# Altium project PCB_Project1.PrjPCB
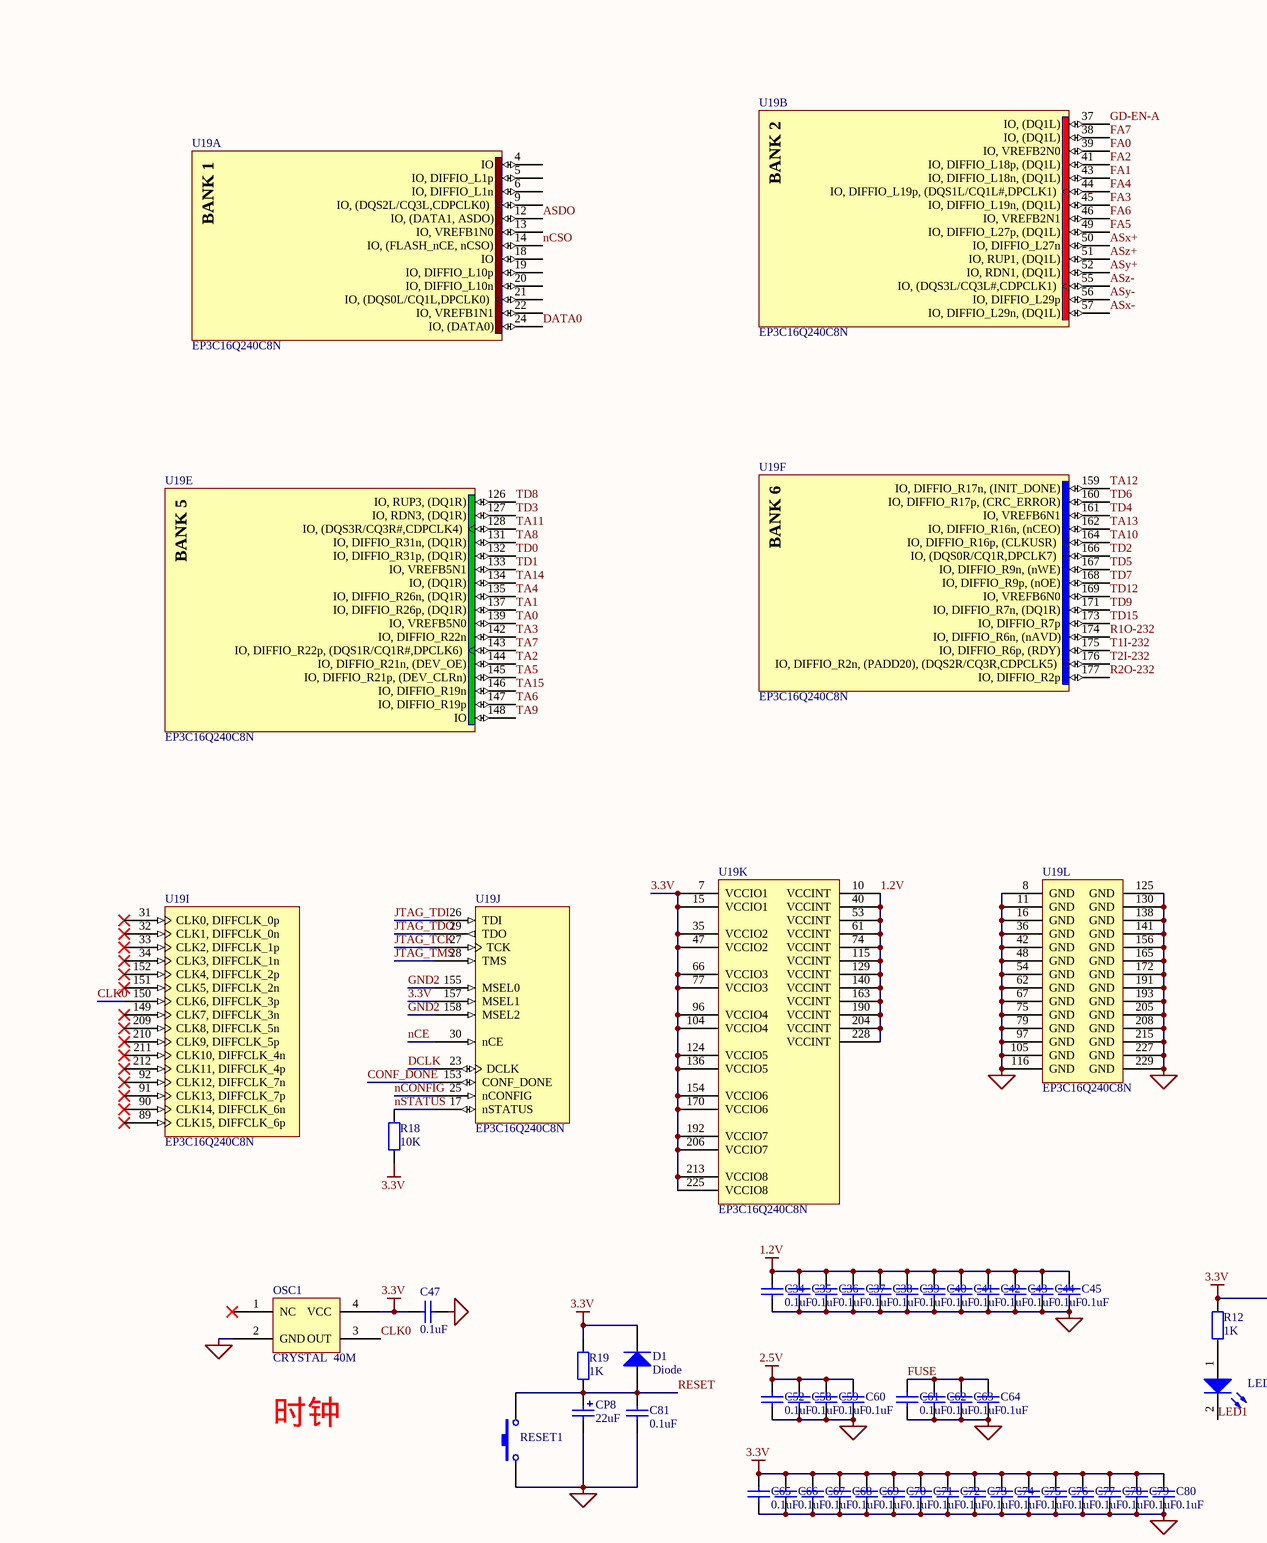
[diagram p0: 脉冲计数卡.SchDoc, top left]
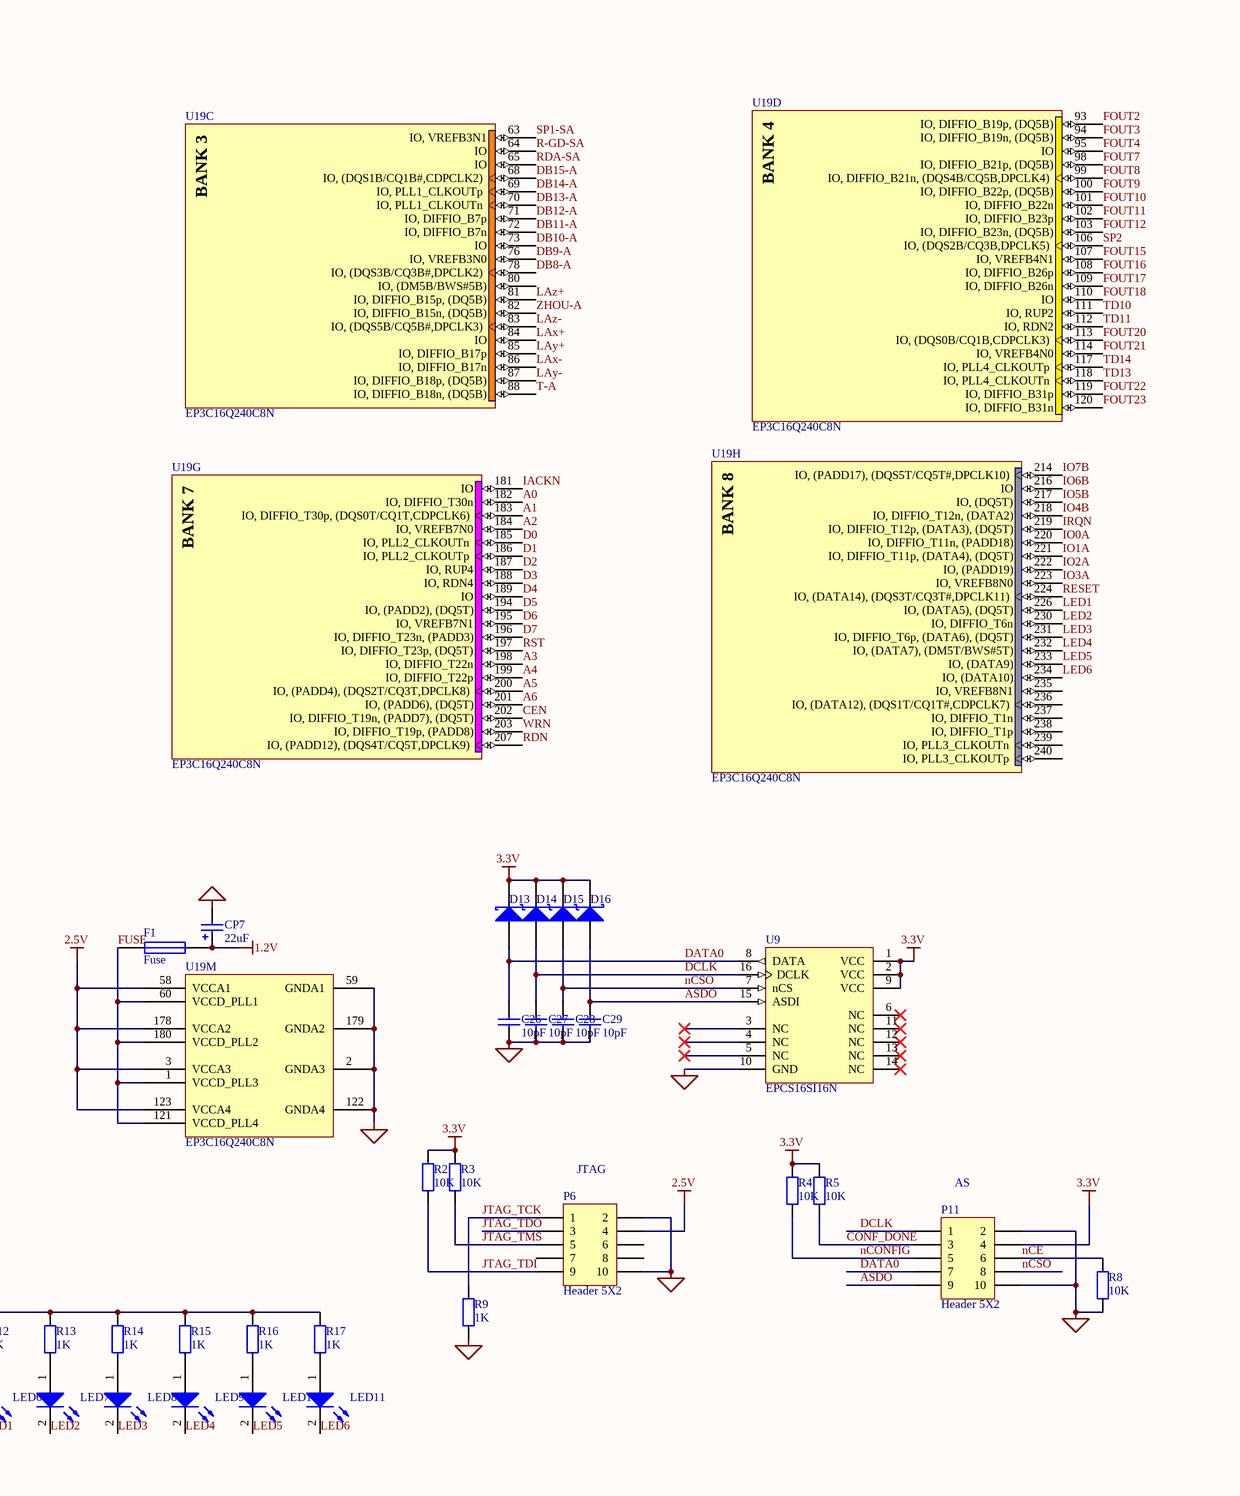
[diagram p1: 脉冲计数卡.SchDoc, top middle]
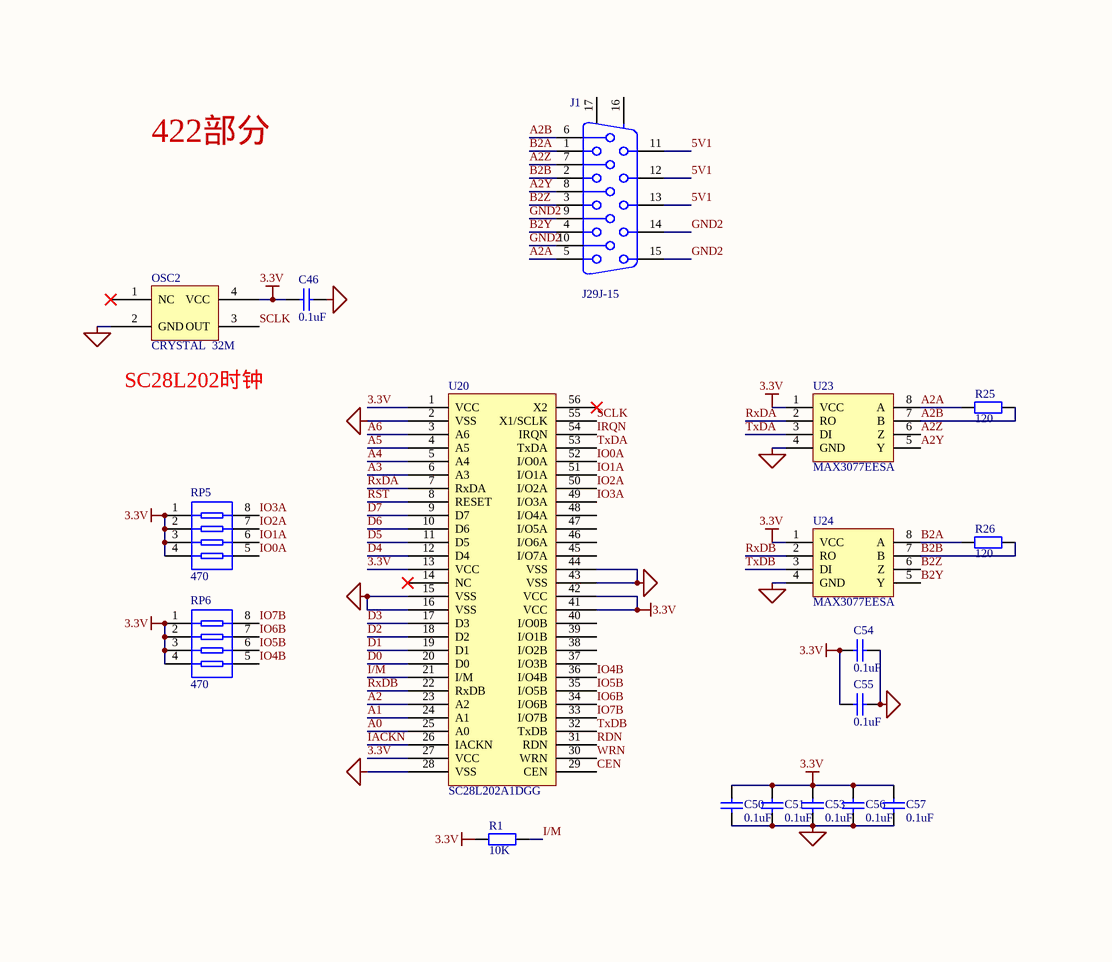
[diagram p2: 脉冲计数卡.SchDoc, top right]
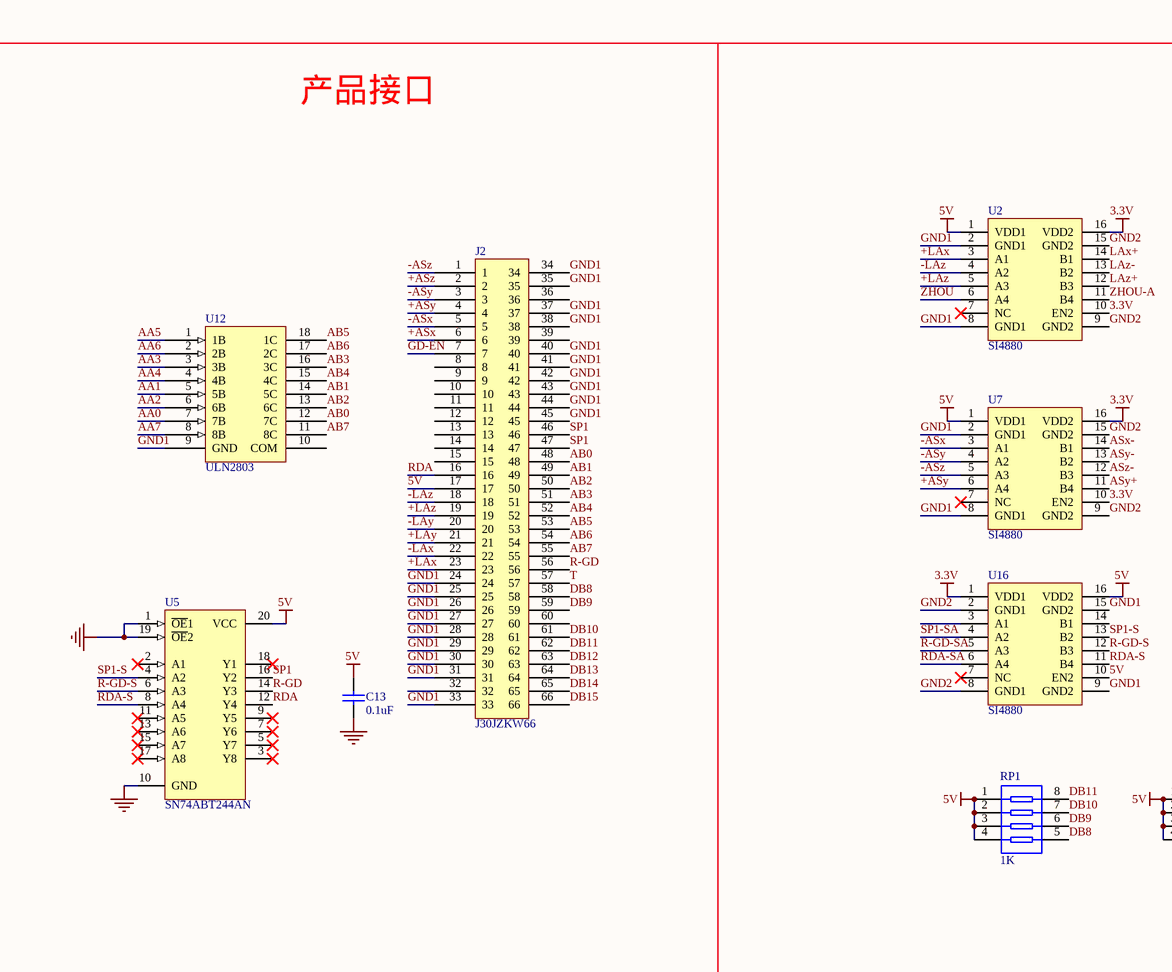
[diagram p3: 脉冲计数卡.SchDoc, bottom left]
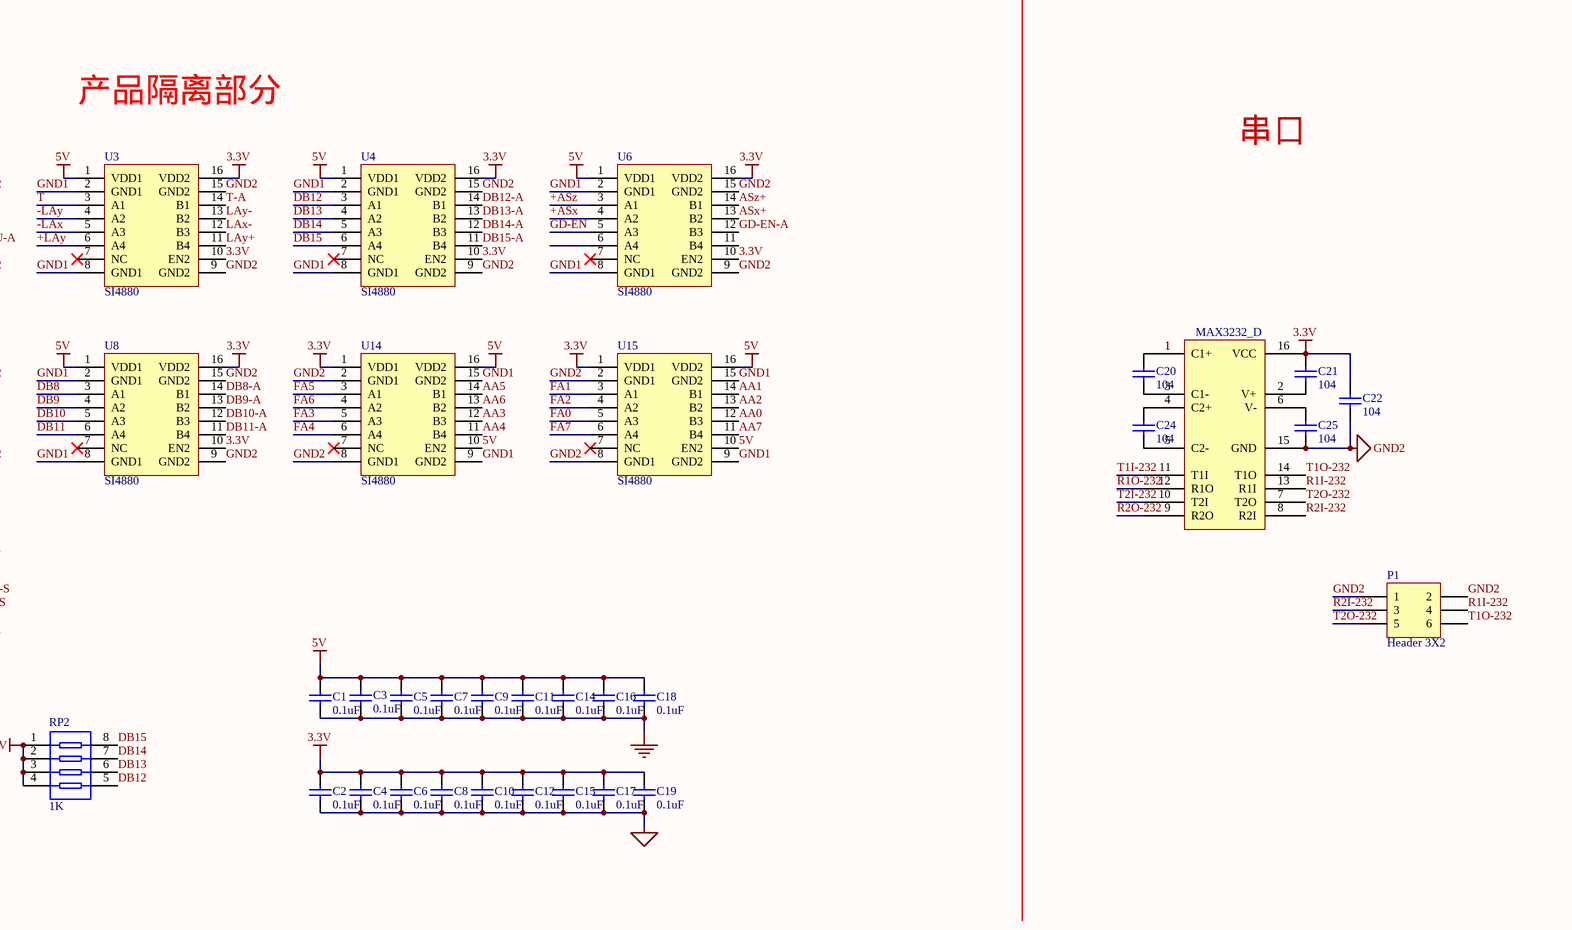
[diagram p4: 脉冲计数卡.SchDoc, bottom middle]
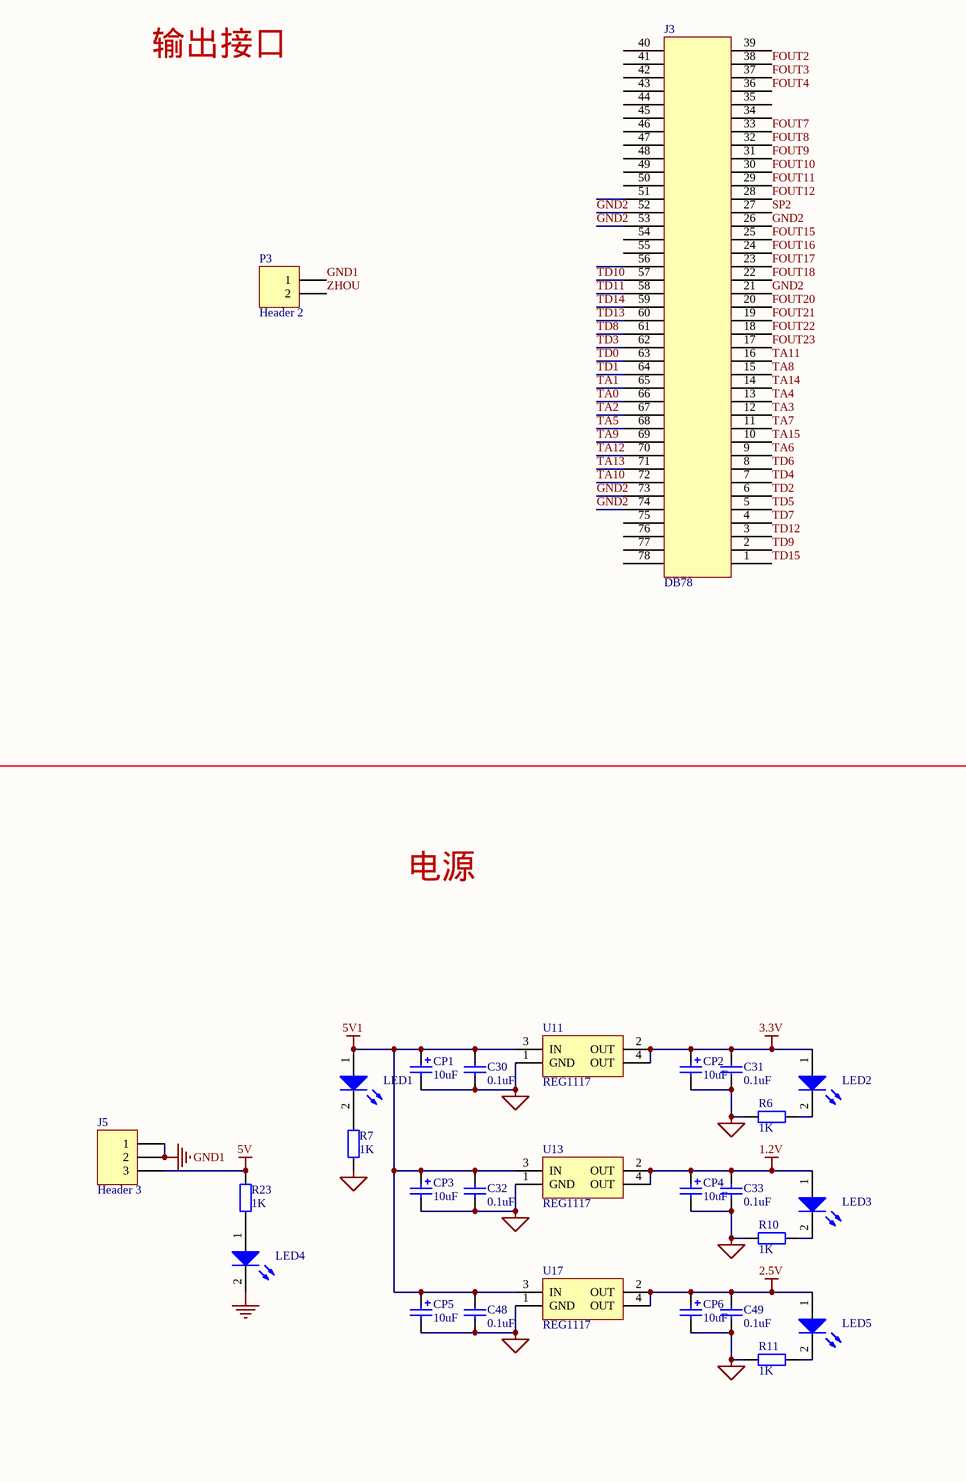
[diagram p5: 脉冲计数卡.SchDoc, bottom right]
1 sheet, 162 parts. Net scope: global (net labels, ports and power ports of the same name join across sheets).
Board file: 脉冲计数卡.PcbDoc

## Sheet 脉冲计数卡.SchDoc
size A1

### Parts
C1  0.1uF  [1608[0603]]
C2  0.1uF  [1608[0603]]
C3  0.1uF  [1608[0603]]
C4  0.1uF  [1608[0603]]
C5  0.1uF  [1608[0603]]
C6  0.1uF  [1608[0603]]
C7  0.1uF  [1608[0603]]
C8  0.1uF  [1608[0603]]
C9  0.1uF  [1608[0603]]
C10  0.1uF  [1608[0603]]
C11  0.1uF  [1608[0603]]
C12  0.1uF  [1608[0603]]
C13  0.1uF  [1608[0603]]
C14  0.1uF  [1608[0603]]
C15  0.1uF  [1608[0603]]
C16  0.1uF  [1608[0603]]
C17  0.1uF  [1608[0603]]
C18  0.1uF  [1608[0603]]
C19  0.1uF  [1608[0603]]
C20  104  [1608[0603]]
C21  104  [1608[0603]]
C22  104  [1608[0603]]
C24  104  [1608[0603]]
C25  104  [1608[0603]]
C26  10pF  [1608[0603]]
C27  10pF  [1608[0603]]
C28  10pF  [1608[0603]]
C29  10pF  [1608[0603]]
C30  0.1uF  [1608[0603]]
C31  0.1uF  [1608[0603]]
C32  0.1uF  [1608[0603]]
C33  0.1uF  [1608[0603]]
C34  0.1uF  [1608[0603]]
C35  0.1uF  [1608[0603]]
C36  0.1uF  [1608[0603]]
C37  0.1uF  [1608[0603]]
C38  0.1uF  [1608[0603]]
C39  0.1uF  [1608[0603]]
C40  0.1uF  [1608[0603]]
C41  0.1uF  [1608[0603]]
C42  0.1uF  [1608[0603]]
C43  0.1uF  [1608[0603]]
C44  0.1uF  [1608[0603]]
C45  0.1uF  [1608[0603]]
C46  0.1uF  [1608[0603]]
C47  0.1uF  [1608[0603]]
C48  0.1uF  [1608[0603]]
C49  0.1uF  [1608[0603]]
C50  0.1uF  [1608[0603]]
C51  0.1uF  [1608[0603]]
C52  0.1uF  [1608[0603]]
C53  0.1uF  [1608[0603]]
C54  0.1uF  [1608[0603]]
C55  0.1uF  [1608[0603]]
C56  0.1uF  [1608[0603]]
C57  0.1uF  [1608[0603]]
C58  0.1uF  [1608[0603]]
C59  0.1uF  [1608[0603]]
C60  0.1uF  [1608[0603]]
C61  0.1uF  [1608[0603]]
C62  0.1uF  [1608[0603]]
C63  0.1uF  [1608[0603]]
C64  0.1uF  [1608[0603]]
C65  0.1uF  [1608[0603]]
C66  0.1uF  [1608[0603]]
C67  0.1uF  [1608[0603]]
C68  0.1uF  [1608[0603]]
C69  0.1uF  [1608[0603]]
C70  0.1uF  [1608[0603]]
C71  0.1uF  [1608[0603]]
C72  0.1uF  [1608[0603]]
C73  0.1uF  [1608[0603]]
C74  0.1uF  [1608[0603]]
C75  0.1uF  [1608[0603]]
C76  0.1uF  [1608[0603]]
C77  0.1uF  [1608[0603]]
C78  0.1uF  [1608[0603]]
C79  0.1uF  [1608[0603]]
C80  0.1uF  [1608[0603]]
C81  0.1uF  [1608[0603]]
CP1  10uF  [C1210]
CP2  10uF  [C1210]
CP3  10uF  [C1210]
CP4  10uF  [C1210]
CP5  10uF  [C1210]
CP6  10uF  [C1210]
CP7  22uF  [C1210]
CP8  22uF  [C1210]
D1  Diode  [DSO-C2/X3.3]
D13  D Schottky  [SMB]  (value not drawn)
D14  D Schottky  [SMB]  (value not drawn)
D15  D Schottky  [SMB]  (value not drawn)
D16  D Schottky  [SMB]  (value not drawn)
F1  Fuse  [R2012-0805]
J1  J29J-15  [J29J-15]
J2  J30JZKW66  [J30J-66ZKW2]
J3  DB78  [DB78]
J5  Header 3  [POWER_CON]
LED1  LED12V  [R2012-0805]  (value not drawn)
LED2  LED12V  [R2012-0805]  (value not drawn)
LED3  LED12V  [R2012-0805]  (value not drawn)
LED4  LED12V  [R2012-0805]  (value not drawn)
LED5  LED12V  [R2012-0805]  (value not drawn)
LED6  LED12V  [R2012-0805]  (value not drawn)
LED7  LED12V  [R2012-0805]  (value not drawn)
LED8  LED12V  [R2012-0805]  (value not drawn)
LED9  LED12V  [R2012-0805]  (value not drawn)
LED10  LED12V  [R2012-0805]  (value not drawn)
LED11  LED12V  [R2012-0805]  (value not drawn)
MAX3232_D  SP3232E  [SOJ-16_2]  (value not drawn)
OSC1  CRYSTAL  40M  [OSC]
OSC2  CRYSTAL  32M  [OSC]
P1  Header 3X2  [HDR2X3]
P3  Header 2  [HDR1X2]
P6  Header 5X2  [FPGA_LOAD]
P11  Header 5X2  [FPGA_LOAD]
R1  10K  [1608[0603]]
R2  10K  [1608[0603]]
R3  10K  [1608[0603]]
R4  10K  [1608[0603]]
R5  10K  [1608[0603]]
R6  1K  [1608[0603]]
R7  1K  [1608[0603]]
R8  10K  [1608[0603]]
R9  1K  [1608[0603]]
R10  1K  [1608[0603]]
R11  1K  [1608[0603]]
R12  1K  [R2012-0805]
R13  1K  [R2012-0805]
R14  1K  [R2012-0805]
R15  1K  [R2012-0805]
R16  1K  [R2012-0805]
R17  1K  [R2012-0805]
R18  10K  [1608[0603]]
R19  1K  [1608[0603]]
R23  1K  [1608[0603]]
R25  120  [1608[0603]]
R26  120  [1608[0603]]
RESET1  SW  [SW4]  (value not drawn)
RP1  1K  [RP8]
RP2  1K  [RP8]
RP5  470  [RP8]
RP6  470  [RP8]
U2  SI4880  [RW-16]
U3  SI4880  [RW-16]
U4  SI4880  [RW-16]
U5  SN74ABT244AN  [SN74ABT244ADW--SOIC20]
U6  SI4880  [RW-16]
U7  SI4880  [RW-16]
U8  SI4880  [RW-16]
U9  EPCS16SI16N  [SOIC16_L]
U11  REG1117  [ZZ311]
U12  ULN2803  [ULN2803AFWG--SOIC18]
U13  REG1117  [ZZ311]
U14  SI4880  [RW-16]
U15  SI4880  [RW-16]
U16  SI4880  [RW-16]
U17  REG1117  [ZZ311]
U19  EP3C16Q240C8N  [PQFP240_N]  (parts A,B,C,D,E,F,G,H,I,J,K,L,M of 13)
U20  SC28L202A1DGG  [TSSOP56]
U23  MAX3077EESA  [DIP8]
U24  MAX3077EESA  [DIP8]

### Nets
1.2V: C33.2 C34.2 C35.2 C36.2 C37.2 C38.2 C39.2 C40.2 C41.2 C42.2 C43.2 C44.2 C45.2 CP4.1 CP7.1 F1.2 LED3.1(A) U13.2(OUT) U13.4(OUT) U19.10(VCCINT) U19.40(VCCINT) U19.53(VCCINT) U19.61(VCCINT) U19.74(VCCINT) U19.115(VCCINT) U19.129(VCCINT) U19.140(VCCINT) U19.163(VCCINT) U19.190(VCCINT) U19.204(VCCINT) U19.228(VCCINT)
2.5V: C49.2 C52.2 C58.2 C59.2 C60.2 CP6.1 LED5.1(A) P6.4 U17.2(OUT) U17.4(OUT) U19.3(VCCA3) U19.58(VCCA1) U19.123(VCCA4) U19.178(VCCA2)
3.3V: C2.2 C4.2 C6.2 C8.2 C10.2 C12.2 C15.2 C17.2 C19.2 C21.2 C22.2 C31.2 C46.1 C47.1 C50.2 C51.2 C53.2 C54.1 C55.1 C56.2 C57.1 C65.2 C66.2 C67.2 C68.2 C69.2 C70.2 C71.2 C72.2 C73.2 C74.2 C75.2 C76.2 C77.2 C78.2 C79.2 C80.2 CP2.1 D1.2(K) D13.2(K) D14.2(K) D15.2(K) D16.2(K) LED2.1(A) MAX3232_D.16(VCC) OSC1.4(VCC) OSC2.4(VCC) P11.4 R1.1 R2.2 R3.2 R4.2 R5.2 R12.2 R13.2 R14.2 R15.2 R16.2 R17.2 R18.1 R19.2 RP5.1 RP5.2 RP5.3 RP5.4 RP6.1 RP6.2 RP6.3 RP6.4 U2.10(EN2) U2.16(VDD2) U3.10(EN2) U3.16(VDD2) U4.10(EN2) U4.16(VDD2) U6.10(EN2) U6.16(VDD2) U7.10(EN2) U7.16(VDD2) U8.10(EN2) U8.16(VDD2) U9.1(VCC) U9.2(VCC) U9.9(VCC) U11.2(OUT) U11.4(OUT) U14.1(VDD1) U15.1(VDD1) U16.1(VDD1) U19.7(VCCIO1) U19.15(VCCIO1) U19.35(VCCIO2) U19.47(VCCIO2) U19.66(VCCIO3) U19.77(VCCIO3) U19.96(VCCIO4) U19.104(VCCIO4) U19.124(VCCIO5) U19.136(VCCIO5) U19.154(VCCIO6) U19.157(MSEL1) U19.170(VCCIO6) U19.192(VCCIO7) U19.206(VCCIO7) U19.213(VCCIO8) U19.225(VCCIO8) U20.1(VCC) U20.13(VCC) U20.27(VCC) U20.41(VCC) U20.42(VCC) U23.1(VCC) U24.1(VCC)
5V: C1.2 C3.2 C5.2 C7.2 C9.2 C11.2 C13.2 C14.2 C16.2 C18.2 J2.17 J5.3 R23.2 RP1.1 RP1.2 RP1.3 RP1.4 RP2.1 RP2.2 RP2.3 RP2.4 U2.1(VDD1) U3.1(VDD1) U4.1(VDD1) U5.20(VCC) U6.1(VDD1) U7.1(VDD1) U8.1(VDD1) U14.10(EN2) U14.16(VDD2) U15.10(EN2) U15.16(VDD2) U16.10(EN2) U16.16(VDD2)
5V1: C30.2 C32.2 C48.2 CP1.1 CP3.1 CP5.1 J1.11 J1.12 J1.13 LED1.1(A) U11.3(IN) U13.3(IN) U17.3(IN)
GND1: C1.1 C3.1 C5.1 C7.1 C9.1 C11.1 C13.1 C14.1 C16.1 C18.1 J2.24 J2.25 J2.26 J2.27 J2.28 J2.29 J2.30 J2.31 J2.33 J2.34 J2.35 J2.37 J2.38 J2.40 J2.41 J2.42 J2.43 J2.44 J2.45 J5.1 J5.2 LED4.2(K) P3.1 U2.2(GND1) U2.8(GND1) U3.2(GND1) U3.8(GND1) U4.2(GND1) U4.8(GND1) U5.1(~{OE}1) U5.10(GND) U5.19(~{OE}2) U6.2(GND1) U6.8(GND1) U7.2(GND1) U7.8(GND1) U8.2(GND1) U8.8(GND1) U12.9(GND) U14.9(GND2) U14.15(GND2) U15.9(GND2) U15.15(GND2) U16.9(GND2) U16.15(GND2)
GND2: C2.1 C4.1 C6.1 C8.1 C10.1 C12.1 C15.1 C17.1 C19.1 C22.1 C25.1 C26.1 C27.1 C28.1 C29.1 C30.1 C31.1 C32.1 C33.1 C34.1 C35.1 C36.1 C37.1 C38.1 C39.1 C40.1 C41.1 C42.1 C43.1 C44.1 C45.1 C46.2 C47.2 C48.1 C49.1 C50.1 C51.1 C52.1 C53.1 C54.2 C55.2 C56.1 C57.2 C58.1 C59.1 C60.1 C61.1 C62.1 C63.1 C64.1 C65.1 C66.1 C67.1 C68.1 C69.1 C70.1 C71.1 C72.1 C73.1 C74.1 C75.1 C76.1 C77.1 C78.1 C79.1 C80.1 C81.1 CP1.2 CP2.2 CP3.2 CP4.2 CP5.2 CP6.2 CP7.2 CP8.2 J1.9 J1.10 J1.14 J1.15 J3.21 J3.26 J3.52 J3.53 J3.73 J3.74 MAX3232_D.15(GND) OSC1.2(GND) OSC2.2(GND) P1.1 P1.2 P6.2 P6.10 P11.2 P11.10 R6.2 R7.2 R8.1 R9.1 R10.2 R11.2 RESET1.1 U2.9(GND2) U2.15(GND2) U3.9(GND2) U3.15(GND2) U4.9(GND2) U4.15(GND2) U6.9(GND2) U6.15(GND2) U7.9(GND2) U7.15(GND2) U8.9(GND2) U8.15(GND2) U9.10(GND) U11.1(GND) U13.1(GND) U14.2(GND1) U14.8(GND1) U15.2(GND1) U15.8(GND1) U16.2(GND1) U16.8(GND1) U17.1(GND) U19.2(GNDA3) U19.8(GND) U19.11(GND) U19.16(GND) U19.36(GND) U19.42(GND) U19.48(GND) U19.54(GND) U19.59(GNDA1) U19.62(GND) U19.67(GND) U19.75(GND) U19.79(GND) U19.97(GND) U19.105(GND) U19.116(GND) U19.122(GNDA4) U19.125(GND) U19.130(GND) U19.138(GND) U19.141(GND) U19.155(MSEL0) U19.156(GND) U19.158(MSEL2) U19.165(GND) U19.172(GND) U19.179(GNDA2) U19.191(GND) U19.193(GND) U19.205(GND) U19.208(GND) U19.215(GND) U19.227(GND) U19.229(GND) U20.2(VSS) U20.15(VSS) U20.16(VSS) U20.28(VSS) U20.43(VSS) U20.44(VSS) U23.4(GND) U24.4(GND)
+ASx: J2.6 U6.4(A2)
+ASy: J2.4 U7.6(A4)
+ASz: J2.2 U6.3(A1)
+LAx: J2.23 U2.3(A1)
+LAy: J2.21 U3.6(A4)
+LAz: J2.19 U2.5(A3)
-ASx: J2.5 U7.3(A1)
-ASy: J2.3 U7.4(A2)
-ASz: J2.1 U7.5(A3)
-LAx: J2.22 U3.5(A3)
-LAy: J2.20 U3.4(A2)
-LAz: J2.18 U2.4(A2)
A0: U19.182(IO,_DIFFIO_T30n) U20.25(A0)
A1: U19.183(IO,_DIFFIO_T30p,_(DQS0T/CQ1T,CDPCLK6)) U20.24(A1)
A2: U19.184(IO,_VREFB7N0) U20.23(A2)
A2A: J1.5 R25.1 U23.8(A)
A2B: J1.6 R25.2 U23.7(B)
A2Y: J1.8 U23.5(Y)
A2Z: J1.7 U23.6(Z)
A3: U19.198(IO,_DIFFIO_T22n) U20.6(A3)
A4: U19.199(IO,_DIFFIO_T22p) U20.5(A4)
A5: U19.200(IO,_(PADD4),_(DQS2T/CQ3T,DPCLK8)) U20.4(A5)
A6: U19.201(IO,_(PADD6),_(DQ5T)) U20.3(A6)
AA0: U12.7(7B) U15.12(B3)
AA1: U12.5(5B) U15.14(B1)
AA2: U12.6(6B) U15.13(B2)
AA3: U12.3(3B) U14.12(B3)
AA4: U12.4(4B) U14.11(B4)
AA5: U12.1(1B) U14.14(B1)
AA6: U12.2(2B) U14.13(B2)
AA7: U12.8(8B) U15.11(B4)
AB0: J2.48 U12.12(7C)
AB1: J2.49 U12.14(5C)
AB2: J2.50 U12.13(6C)
AB3: J2.51 U12.16(3C)
AB4: J2.52 U12.15(4C)
AB5: J2.53 U12.18(1C)
AB6: J2.54 U12.17(2C)
AB7: J2.55 U12.11(8C)
ASDO: C29.2 D16.1(A) P11.9 U9.15(ASDI) U19.12(IO,_(DATA1,_ASDO))
ASx+: U6.13(B2) U19.50(IO,_DIFFIO_L27n)
ASx-: U7.14(B1) U19.57(IO,_DIFFIO_L29n,_(DQ1L))
ASy+: U7.11(B4) U19.52(IO,_RDN1,_(DQ1L))
ASy-: U7.13(B2) U19.56(IO,_DIFFIO_L29p)
ASz+: U6.14(B1) U19.51(IO,_RUP1,_(DQ1L))
ASz-: U7.12(B3) U19.55(IO,_(DQS3L/CQ3L#,CDPCLK1))
B2A: J1.1 R26.1 U24.8(A)
B2B: J1.2 R26.2 U24.7(B)
B2Y: J1.4 U24.5(Y)
B2Z: J1.3 U24.6(Z)
CEN: U19.202(IO,_DIFFIO_T19n,_(PADD7),_(DQ5T)) U20.29(CEN)
CLK0: OSC1.3(OUT) U19.150(CLK6,_DIFFCLK_3p)
CONF_DONE: P11.3 R5.1 U19.153(CONF_DONE)
D0: U19.185(IO,_PLL2_CLKOUTn) U20.20(D0)
D1: U19.186(IO,_PLL2_CLKOUTp) U20.19(D1)
D2: U19.187(IO,_RUP4) U20.18(D2)
D3: U19.188(IO,_RDN4) U20.17(D3)
D4: U19.189(IO) U20.12(D4)
D5: U19.194(IO,_(PADD2),_(DQ5T)) U20.11(D5)
D6: U19.195(IO,_VREFB7N1) U20.10(D6)
D7: U19.196(IO,_DIFFIO_T23n,_(PADD3)) U20.9(D7)
DATA0: C26.2 D13.1(A) P11.7 U9.8(DATA) U19.24(IO,_(DATA0))
DB8: J2.58 RP1.5 U8.3(A1)
DB8-A: U8.14(B1) U19.78(IO,_(DQS3B/CQ3B#,DPCLK2))
DB9: J2.59 RP1.6 U8.4(A2)
DB9-A: U8.13(B2) U19.76(IO,_VREFB3N0)
DB10: J2.61 RP1.7 U8.5(A3)
DB10-A: U8.12(B3) U19.73(IO)
DB11: J2.62 RP1.8 U8.6(A4)
DB11-A: U8.11(B4) U19.72(IO,_DIFFIO_B7n)
DB12: J2.63 RP2.5 U4.3(A1)
DB12-A: U4.14(B1) U19.71(IO,_DIFFIO_B7p)
DB13: J2.64 RP2.6 U4.4(A2)
DB13-A: U4.13(B2) U19.70(IO,_PLL1_CLKOUTn)
DB14: J2.65 RP2.7 U4.5(A3)
DB14-A: U4.12(B3) U19.69(IO,_PLL1_CLKOUTp)
DB15: J2.66 RP2.8 U4.6(A4)
DB15-A: U4.11(B4) U19.68(IO,_(DQS1B/CQ1B#,CDPCLK2))
DCLK: C27.2 D14.1(A) P11.1 U9.16(DCLK) U19.23(DCLK)
FA0: U15.5(A3) U19.39(IO,_VREFB2N0)
FA1: U15.3(A1) U19.43(IO,_DIFFIO_L18n,_(DQ1L))
FA2: U15.4(A2) U19.41(IO,_DIFFIO_L18p,_(DQ1L))
FA3: U14.5(A3) U19.45(IO,_DIFFIO_L19n,_(DQ1L))
FA4: U14.6(A4) U19.44(IO,_DIFFIO_L19p,_(DQS1L/CQ1L#,DPCLK1))
FA5: U14.3(A1) U19.49(IO,_DIFFIO_L27p,_(DQ1L))
FA6: U14.4(A2) U19.46(IO,_VREFB2N1)
FA7: U15.6(A4) U19.38(IO,_(DQ1L))
FOUT2: J3.38 U19.93(IO,_DIFFIO_B19p,_(DQ5B))
FOUT3: J3.37 U19.94(IO,_DIFFIO_B19n,_(DQ5B))
FOUT4: J3.36 U19.95(IO)
FOUT7: J3.33 U19.98(IO,_DIFFIO_B21p,_(DQ5B))
FOUT8: J3.32 U19.99(IO,_DIFFIO_B21n,_(DQS4B/CQ5B,DPCLK4))
FOUT9: J3.31 U19.100(IO,_DIFFIO_B22p,_(DQ5B))
FOUT10: J3.30 U19.101(IO,_DIFFIO_B22n)
FOUT11: J3.29 U19.102(IO,_DIFFIO_B23p)
FOUT12: J3.28 U19.103(IO,_DIFFIO_B23n,_(DQ5B))
FOUT15: J3.25 U19.107(IO,_VREFB4N1)
FOUT16: J3.24 U19.108(IO,_DIFFIO_B26p)
FOUT17: J3.23 U19.109(IO,_DIFFIO_B26n)
FOUT18: J3.22 U19.110(IO)
FOUT20: J3.20 U19.113(IO,_(DQS0B/CQ1B,CDPCLK3))
FOUT21: J3.19 U19.114(IO,_VREFB4N0)
FOUT22: J3.18 U19.119(IO,_DIFFIO_B31p)
FOUT23: J3.17 U19.120(IO,_DIFFIO_B31n)
FUSE: C61.2 C62.2 C63.2 C64.2 F1.1 U19.1(VCCD_PLL3) U19.60(VCCD_PLL1) U19.121(VCCD_PLL4) U19.180(VCCD_PLL2)
GD-EN: J2.7 U6.5(A3)
GD-EN-A: U6.12(B3) U19.37(IO,_(DQ1L))
I/M: R1.2 U20.21(I/M)
IACKN: U19.181(IO) U20.26(IACKN)
IO0A: RP5.5 U19.220(IO,_DIFFIO_T11n,_(PADD18)) U20.52(I/O0A)
IO1A: RP5.6 U19.221(IO,_DIFFIO_T11p,_(DATA4),_(DQ5T)) U20.51(I/O1A)
IO2A: RP5.7 U19.222(IO,_(PADD19)) U20.50(I/O2A)
IO3A: RP5.8 U19.223(IO,_VREFB8N0) U20.49(I/O3A)
IO4B: RP6.5 U19.218(IO,_DIFFIO_T12n,_(DATA2)) U20.36(I/O4B)
IO5B: RP6.6 U19.217(IO,_(DQ5T)) U20.35(I/O5B)
IO6B: RP6.7 U19.216(IO) U20.34(I/O6B)
IO7B: RP6.8 U19.214(IO,_(PADD17),_(DQS5T/CQ5T#,DPCLK10)) U20.33(I/O7B)
IRQN: U19.219(IO,_DIFFIO_T12p,_(DATA3),_(DQ5T)) U20.54(IRQN)
JTAG_TCK: P6.1 R9.2 U19.27(TCK)
JTAG_TDI: P6.9 R2.1 U19.26(TDI)
JTAG_TDO: P6.3 U19.29(TDO)
JTAG_TMS: P6.5 R3.1 U19.28(TMS)
LAx+: U2.14(B1) U19.84(IO)
LAx-: U3.12(B3) U19.86(IO,_DIFFIO_B17n)
LAy+: U3.11(B4) U19.85(IO,_DIFFIO_B17p)
LAy-: U3.13(B2) U19.87(IO,_DIFFIO_B18p,_(DQ5B))
LAz+: U2.12(B3) U19.81(IO,_DIFFIO_B15p,_(DQ5B))
LAz-: U2.13(B2) U19.83(IO,_(DQS5B/CQ5B#,DPCLK3))
LED1: LED6.2(K) U19.226(IO,_(DATA5),_(DQ5T))
LED2: LED7.2(K) U19.230(IO,_DIFFIO_T6n)
LED3: LED8.2(K) U19.231(IO,_DIFFIO_T6p,_(DATA6),_(DQ5T))
LED4: LED9.2(K) U19.232(IO,_(DATA7),_(DM5T/BWS#5T))
LED5: LED10.2(K) U19.233(IO,_(DATA9))
LED6: LED11.2(K) U19.234(IO,_(DATA10))
nCE: P11.6 R8.2 U19.30(nCE)
nCONFIG: P11.5 R4.1 U19.25(nCONFIG)
nCSO: C28.2 D15.1(A) P11.8 U9.7(nCS) U19.14(IO,_(FLASH_nCE,_nCSO))
nSTATUS: R18.2 U19.17(nSTATUS)
R1I-232: MAX3232_D.13(R1I) P1.4
R1O-232: MAX3232_D.12(R1O) U19.174(IO,_DIFFIO_R6n,_(nAVD))
R2I-232: MAX3232_D.8(R2I) P1.3
R2O-232: MAX3232_D.9(R2O) U19.177(IO,_DIFFIO_R2p)
R-GD: J2.56 U5.14(Y3)
R-GD-S: U5.6(A3) U16.12(B3)
R-GD-SA: U16.5(A3) U19.64(IO)
RDA: J2.16 U5.12(Y4)
RDA-S: U5.8(A4) U16.11(B4)
RDA-SA: U16.6(A4) U19.65(IO)
RDN: U19.207(IO,_(PADD12),_(DQS4T/CQ5T,DPCLK9)) U20.31(RDN)
RESET: C81.2 CP8.1 D1.1(A) R19.1 RESET1.2 U19.224(IO,_(DATA14),_(DQS3T/CQ3T#,DPCLK11))
RST: U19.197(IO,_DIFFIO_T23p,_(DQ5T)) U20.8(RESET)
RxDA: U20.7(RxDA) U23.2(RO)
RxDB: U20.22(RxDB) U24.2(RO)
SCLK: OSC2.3(OUT) U20.55(X1/SCLK)
SP1: J2.46 J2.47 U5.16(Y2)
SP1-S: U5.4(A2) U16.13(B2)
SP1-SA: U16.4(A2) U19.63(IO,_VREFB3N1)
SP2: J3.27 U19.106(IO,_(DQS2B/CQ3B,DPCLK5))
T: J2.57 U3.3(A1)
T1I-232: MAX3232_D.11(T1I) U19.175(IO,_DIFFIO_R6p,_(RDY))
T1O-232: MAX3232_D.14(T1O) P1.6
T2I-232: MAX3232_D.10(T2I) U19.176(IO,_DIFFIO_R2n,_(PADD20),_(DQS2R/CQ3R,CDPCLK5))
T2O-232: MAX3232_D.7(T2O) P1.5
T-A: U3.14(B1) U19.88(IO,_DIFFIO_B18n,_(DQ5B))
TA0: J3.66 U19.139(IO,_VREFB5N0)
TA1: J3.65 U19.137(IO,_DIFFIO_R26p,_(DQ1R))
TA2: J3.67 U19.144(IO,_DIFFIO_R21n,_(DEV_OE))
TA3: J3.12 U19.142(IO,_DIFFIO_R22n)
TA4: J3.13 U19.135(IO,_DIFFIO_R26n,_(DQ1R))
TA5: J3.68 U19.145(IO,_DIFFIO_R21p,_(DEV_CLRn))
TA6: J3.9 U19.147(IO,_DIFFIO_R19p)
TA7: J3.11 U19.143(IO,_DIFFIO_R22p,_(DQS1R/CQ1R#,DPCLK6))
TA8: J3.15 U19.131(IO,_DIFFIO_R31n,_(DQ1R))
TA9: J3.69 U19.148(IO)
TA10: J3.72 U19.164(IO,_DIFFIO_R16p,_(CLKUSR))
TA11: J3.16 U19.128(IO,_(DQS3R/CQ3R#,CDPCLK4))
TA12: J3.70 U19.159(IO,_DIFFIO_R17n,_(INIT_DONE))
TA13: J3.71 U19.162(IO,_DIFFIO_R16n,_(nCEO))
TA14: J3.14 U19.134(IO,_(DQ1R))
TA15: J3.10 U19.146(IO,_DIFFIO_R19n)
TD0: J3.63 U19.132(IO,_DIFFIO_R31p,_(DQ1R))
TD1: J3.64 U19.133(IO,_VREFB5N1)
TD2: J3.6 U19.166(IO,_(DQS0R/CQ1R,DPCLK7))
TD3: J3.62 U19.127(IO,_RDN3,_(DQ1R))
TD4: J3.7 U19.161(IO,_VREFB6N1)
TD5: J3.5 U19.167(IO,_DIFFIO_R9n,_(nWE))
TD6: J3.8 U19.160(IO,_DIFFIO_R17p,_(CRC_ERROR))
TD7: J3.4 U19.168(IO,_DIFFIO_R9p,_(nOE))
TD8: J3.61 U19.126(IO,_RUP3,_(DQ1R))
TD9: J3.2 U19.171(IO,_DIFFIO_R7n,_(DQ1R))
TD10: J3.57 U19.111(IO,_RUP2)
TD11: J3.58 U19.112(IO,_RDN2)
TD12: J3.3 U19.169(IO,_VREFB6N0)
TD13: J3.60 U19.118(IO,_PLL4_CLKOUTn)
TD14: J3.59 U19.117(IO,_PLL4_CLKOUTp)
TD15: J3.1 U19.173(IO,_DIFFIO_R7p)
TxDA: U20.53(TxDA) U23.3(DI)
TxDB: U20.32(TxDB) U24.3(DI)
WRN: U19.203(IO,_DIFFIO_T19p,_(PADD8)) U20.30(WRN)
ZHOU: P3.2 U2.6(A4)
ZHOU-A: U2.11(B4) U19.82(IO,_DIFFIO_B15n,_(DQ5B))
NetC20_1: C20.1 MAX3232_D.3(C1-)
NetC20_2: C20.2 MAX3232_D.1(C1+)
NetC21_1: C21.1 MAX3232_D.2(V+)
NetC24_1: C24.1 MAX3232_D.5(C2-)
NetC24_2: C24.2 MAX3232_D.4(C2+)
NetC25_2: C25.2 MAX3232_D.6(V-)
NetLED1_2: LED1.2(K) R7.1
NetLED2_2: LED2.2(K) R6.1
NetLED3_2: LED3.2(K) R10.1
NetLED4_1: LED4.1(A) R23.1
NetLED5_2: LED5.2(K) R11.1
NetLED6_1: LED6.1(A) R12.1
NetLED7_1: LED7.1(A) R13.1
NetLED8_1: LED8.1(A) R14.1
NetLED9_1: LED9.1(A) R15.1
NetLED10_1: LED10.1(A) R16.1
NetLED11_1: LED11.1(A) R17.1

Not connected (* = marked no-connect by the designer): J1 16(MH1) 17(MH2); J2 8 9 10 11 12 13 14 15 32 36 39 60; J3 34 35 39 40 41 42 43 44 45 46 47 48 49 50 51 54 55 56 75 76 77 78; OSC1 1(NC)*; OSC2 1(NC)*; P6 6 7 8; U2 7(NC)*; U3 7(NC)*; U4 7(NC)*; U5 2(A1)* 3(Y8)* 5(Y7)* 7(Y6)* 9(Y5)* 11(A5)* 13(A6)* 15(A7)* 17(A8)* 18(Y1)*; U6 6(A4) 7(NC)* 11(B4); U7 7(NC)*; U8 7(NC)*; U9 3(NC)* 4(NC)* 5(NC)* 6(NC)* 11(NC)* 12(NC)* 13(NC)* 14(NC)*; U12 10(COM); U14 7(NC)*; U15 7(NC)*; U16 3(A1) 7(NC)* 14(B1); U19 4(IO) 5(IO,_DIFFIO_L1p) 6(IO,_DIFFIO_L1n) 9(IO,_(DQS2L/CQ3L,CDPCLK0)) 13(IO,_VREFB1N0) 18(IO) 19(IO,_DIFFIO_L10p) 20(IO,_DIFFIO_L10n) 21(IO,_(DQS0L/CQ1L,DPCLK0)) 22(IO,_VREFB1N1) 31(CLK0,_DIFFCLK_0p)* 32(CLK1,_DIFFCLK_0n)* 33(CLK2,_DIFFCLK_1p)* 34(CLK3,_DIFFCLK_1n)* 80(IO,_(DM5B/BWS#5B)) 89(CLK15,_DIFFCLK_6p)* 90(CLK14,_DIFFCLK_6n)* 91(CLK13,_DIFFCLK_7p)* 92(CLK12,_DIFFCLK_7n)* 149(CLK7,_DIFFCLK_3n)* 151(CLK5,_DIFFCLK_2n)* 152(CLK4,_DIFFCLK_2p)* 209(CLK8,_DIFFCLK_5n)* 210(CLK9,_DIFFCLK_5p)* 211(CLK10,_DIFFCLK_4n)* 212(CLK11,_DIFFCLK_4p)* 235(IO,_VREFB8N1) 236(IO,_(DATA12),_(DQS1T/CQ1T#,CDPCLK7)) 237(IO,_DIFFIO_T1n) 238(IO,_DIFFIO_T1p) 239(IO,_PLL3_CLKOUTn) 240(IO,_PLL3_CLKOUTp); U20 14(NC)* 37(I/O3B) 38(I/O2B) 39(I/O1B) 40(I/O0B) 45(I/O7A) 46(I/O6A) 47(I/O5A) 48(I/O4A) 56(X2)*

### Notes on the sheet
- 422部分
- (near OSC2) SC28L202时钟
- (near P6) JTAG
- (near P11) AS
- 输出接口
- 时钟
- 产品接口
- 产品隔离部分
- 电源
- 串口

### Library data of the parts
C1-C22 C24-C81 = Cap: Capacitor; Manufacturer: Generic Components; Value: 100pF; Class: Passive
CP1-CP6 = Cap Pol3: Polarized Capacitor (Surface Mount); Manufacturer: Generic Components; Class: Passive
CP7 CP8 = Cap Pol3: Polarized Capacitor (Surface Mount); Manufacturer: Generic Components; Class: Passive; Value: 10uF
D1 = Diode: Default Diode; Manufacturer: Generic Components; Class: Discrete; SubClass: Diode - Switching
D13-D16 = D Schottky: Schottky Diode
J1 = Connector 15: Receptacle Assembly, 15-Pin, Sim Line Connector; PackageDocument: B; Positions: 15; Gender: Receptacle Header
LED1-LED11 = LED2: Typical RED, GREEN, YELLOW, AMBER GaAs LED; Manufacturer: Generic Components; Class: Optoelectronic
MAX3232_D = MAX3232
OSC1 OSC2 = CRYSTAL4
P1 = Header 3X2: Header, 3-Pin, Dual row
P3 = Header 2: Header, 2-Pin
P6 P11 = Header 5X2: Header, 5-Pin, Dual row
R1-R19 = Res2: Resistor; Value: 120
R23 R25 R26 = Res2: Resistor
RESET1 = SW: Switch; Manufacturer: Generic Components
RP1 RP2 RP5 RP6 = RESPACK8
U5 = SN74ABT244AN: Octal Buffer/Driver with 3-State Outputs; Package Information: Latest Revision: Oct-1995
U9 = EPCS16SI16N: EPCS16 Series, In-system programmable 3.3V serial configuration device, 16-Pin SOIC, 16-Megabit, Industrial Grade, Pb-Free; Configures: Cyclone II, Stratix II, & Cyclone Devices
U12 = ULN2803A: Darlington transistor array
U19 = EP3C16Q240C8N: Cyclone III Family FPGA, 160 I/O Pins, 4 PLLs, 240-Pin PQFP, Speed Grade 8, Commercial Grade, Pb-Free
U20 = SC28L202
U23 U24 = MAX3077E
